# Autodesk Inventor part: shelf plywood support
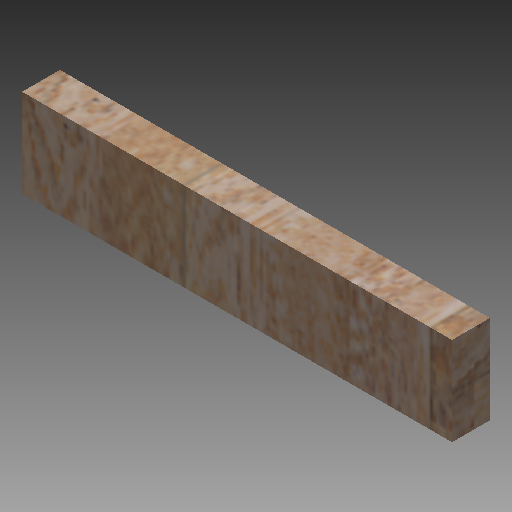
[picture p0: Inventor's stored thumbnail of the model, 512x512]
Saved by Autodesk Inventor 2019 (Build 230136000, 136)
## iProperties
Created: 2013-07
Part Number: shelf plywood support
Material: Generic
Document SubType Name: Modeling
Designer: Patrick Rice
Density: 1 g/cm^3
Appearance: Red Oak - Natural
Author: Patrick Rice
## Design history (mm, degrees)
sketch "Sketch1"
  geometry: L1 (44.45, -19.05)-(-44.45, -19.05); L2 (-44.45, -19.05)-(-44.45, 19.05); L3 (-44.45, 19.05)-(44.45, 19.05); L4 (44.45, 19.05)-(44.45, -19.05); L5 (44.45, -19.05)-(-44.45, 19.05); L6 (-44.45, -19.05)-(44.45, 19.05); 1 further point
  constraints: 12 end point, 2 midpoint, 2 parallel, 1 horizontal, 1 perpendicular
  dimensions: "d0" = 88.9 distance of L2.end L3.end; "d1" = 38.1 distance of L1.end L2.end
extrude "Extrusion1" new body sketch "Sketch1" distance "d2" = 431.8; taper "d3" = 0 deg
body "Solid1"
